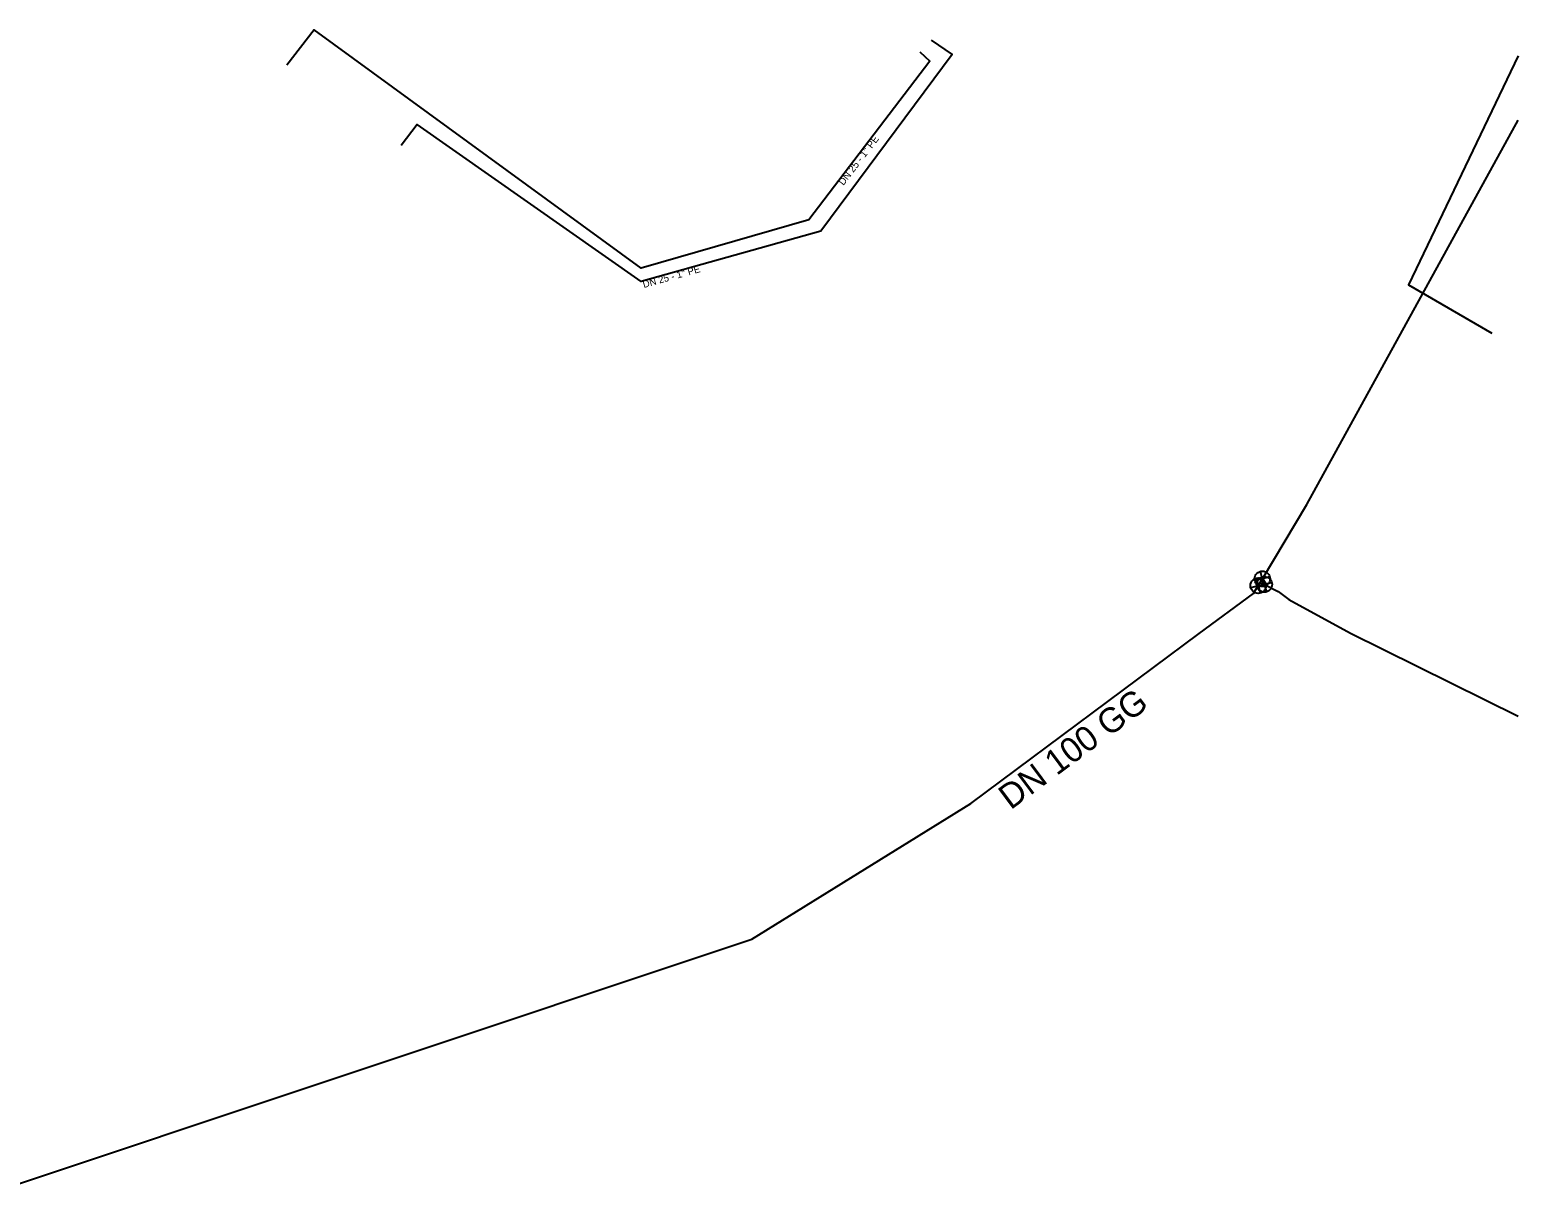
# Model space of a CAD drawing. Extents: x -508836 to -508629, y -1104379 to -1104257.
# Drawn here: x -508725.2 to -508629.2, y -1104344.8 to -1104269.1 of the extents above; entities that cross this region are included whole.
import ezdxf

# ---------------------------------------------------------------- set-up
doc = ezdxf.new("R2010")
doc.units = 0
for name, color, linetype in [('_pripojka_priblizne_', 7, 'Continuous'), ('_voda_provozovana_prevzato_z_dokumentace_', 7, 'Continuous'), ('_voda_smvak_prevzato_z_dokumentace_', 7, 'Continuous'), ('Default', 7, 'Continuous'), ('MoLevel 27', 7, 'Continuous'), ('MoLevel 32', 7, 'Continuous'), ('MoLevel 46', 7, 'Continuous')]:
    doc.layers.add(name, color=color, linetype=linetype)

# ---------------------------------------------------------------- blocks, each defined once
blk = doc.blocks.new('_uzaver_')
at = {"layer": 'Default'}
for p, q in [((-0.000035, -0.000035), (0.000035, 0.000035)), ((0.000035, -0.000035), (-0.000035, 0.000035))]:
    blk.add_line(p, q, dxfattribs=at)
for radius in [0.00005, 0.0000025]:
    blk.add_circle((0, 0), radius, dxfattribs=at)

msp = doc.modelspace()

# ---------------------------------------------------------------- linework, layer by layer
at = {"layer": '_pripojka_priblizne_'}
for points in [[(-508667.817, -1104270.573), (-508667.177, -1104271.172), (-508674.988, -1104281.396), (-508685.784, -1104284.508), (-508706.868, -1104269.14), (-508708.647, -1104271.426)], [(-508667.1, -1104269.803), (-508665.729, -1104270.74), (-508674.213, -1104282.12), (-508685.797, -1104285.372), (-508700.226, -1104275.244), (-508701.272, -1104276.614)], [(-508629.231, -1104270.817), (-508636.303, -1104285.596), (-508630.934, -1104288.7)]]:
    msp.add_lwpolyline(points, dxfattribs=at)
at = {"layer": '_voda_provozovana_prevzato_z_dokumentace_'}
for p, q in [((-508645.87, -1104304.78), (-508645.6, -1104304.91)), ((-508645.6, -1104304.91), (-508644.71, -1104305.37)), ((-508640.05, -1104308.06), (-508629.231, -1104313.416))]:
    msp.add_line(p, q, dxfattribs=at)
msp.add_lwpolyline([(-508644.71, -1104305.37), (-508644.03, -1104305.89), (-508640.05, -1104308.06)], dxfattribs=at)
at = {"layer": '_voda_smvak_prevzato_z_dokumentace_'}
for p, q in [((-508642.86, -1104299.76), (-508629.231, -1104274.96)), ((-508645.73, -1104304.55), (-508642.86, -1104299.76)), ((-508645.87, -1104304.78), (-508645.73, -1104304.55)), ((-508646, -1104304.99), (-508645.87, -1104304.78))]:
    msp.add_line(p, q, dxfattribs=at)
for points in [[(-508649.8, -1104308.07), (-508646.31, -1104305.5), (-508646, -1104304.99)], [(-508729.521, -1104344.755), (-508678.664, -1104327.789), (-508664.537, -1104319.037), (-508649.8, -1104308.07)]]:
    msp.add_lwpolyline(points, dxfattribs=at)

# ---------------------------------------------------------------- block references
at = {"layer": 'MoLevel 27', "xscale": 10000}
for p, yscale, rotation in [((-508646, -1104304.99), 10000, -121.29303898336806), ((-508645.73, -1104304.55), 10000.000000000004, 59.0714374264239), ((-508645.6, -1104304.91), 10000, -27.33235948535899)]:
    msp.add_blockref('_uzaver_', p, dxfattribs=dict(at, yscale=yscale, rotation=rotation))

# ---------------------------------------------------------------- texts
at = {"layer": 'MoLevel 32'}
for rotation, p in [(52.62107, (-508672.746, -1104279.212)), (15.67953, (-508685.618, -1104285.794))]:
    msp.add_text("DN 25 - 1'' PE", height=0.455, rotation=rotation, dxfattribs=at).set_placement(p)
at = {"layer": 'MoLevel 46'}
msp.add_text('DN 100 GG', height=1.6049, rotation=36.65593, dxfattribs=at).set_placement((-508661.964, -1104319.487))

doc.saveas('drawing.dxf')
